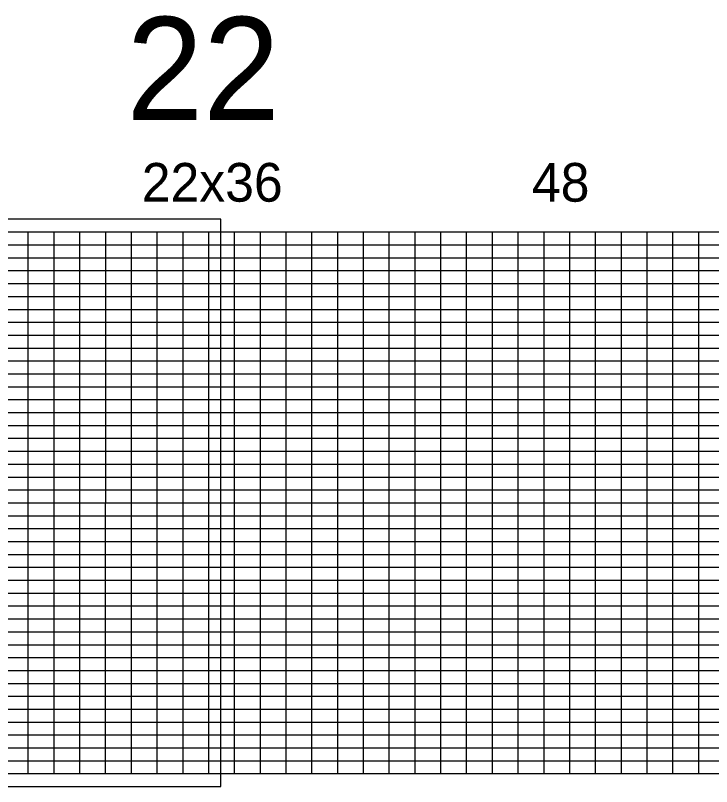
# Model space of a CAD drawing. Extents: x 1914168 to 1925341, y 720939 to 777401.
# Drawn here: x 1921169 to 1922519, y 733439 to 734934 of the extents above; entities that cross this region are included whole.
import ezdxf

# ---------------------------------------------------------------- set-up
doc = ezdxf.new("R2010")
doc.units = 0
for name, color, linetype in [('RD_PD_ALT1_CL', 7, 'Continuous'), ('RD_PD_WallFill', 7, 'Continuous'), ('RD_SHT_IplotShp', 7, 'Continuous')]:
    doc.layers.add(name, color=color, linetype=linetype)

msp = doc.modelspace()

# ---------------------------------------------------------------- linework, layer by layer
at = {"layer": 'RD_PD_WallFill'}
for p, q in [((1919844.1, 734514.2), (1925194.1, 734514.2)), ((1919844.1, 734514.2), (1921594.1, 734514.2)), ((1921194, 733464.2), (1921194.1, 734514.2)), ((1921194, 733464.2), (1921194.1, 734514.2)), ((1921244.1, 733464.2), (1921244.1, 734514.2)), ((1921244.1, 733464.2), (1921244.1, 734514.2)), ((1921294.1, 733464.2), (1921294.1, 734514.2)), ((1921294.1, 733464.2), (1921294.1, 734514.2)), ((1921344, 733464.2), (1921344.1, 734514.2)), ((1921344, 733464.2), (1921344.1, 734514.2)), ((1921394, 733464.2), (1921394.1, 734514.2)), ((1921394, 733464.2), (1921394.1, 734514.2)), ((1921444.1, 733464.2), (1921444.1, 734514.2)), ((1921444.1, 733464.2), (1921444.1, 734514.2)), ((1921494.1, 733464.2), (1921494.1, 734514.2)), ((1921494.1, 733464.2), (1921494.1, 734514.2)), ((1921544.1, 733464.2), (1921544.1, 734514.2)), ((1921544.1, 733464.2), (1921544.1, 734514.2)), ((1921594.1, 733464.2), (1921594.1, 734514.2)), ((1921594.1, 733464.2), (1921594.1, 734514.2)), ((1921644.1, 733464.2), (1921644.1, 734514.2)), ((1921644.1, 733464.2), (1921644.1, 734514.2)), ((1921694.1, 733464.2), (1921694.1, 734514.2)), ((1921694.1, 733464.2), (1921694.1, 734514.2)), ((1921744.1, 733464.2), (1921744.1, 734514.2)), ((1921744.1, 733464.2), (1921744.1, 734514.2)), ((1921794.1, 733464.2), (1921794.1, 734514.2)), ((1921794.1, 733464.2), (1921794.1, 734514.2)), ((1921844.1, 733464.2), (1921844.1, 734514.2)), ((1921844.1, 733464.2), (1921844.1, 734514.2)), ((1921894.1, 733464.2), (1921894.1, 734514.2)), ((1921894.1, 733464.2), (1921894.1, 734514.2)), ((1921944.1, 733464.2), (1921944.1, 734514.2)), ((1921944.1, 733464.2), (1921944.1, 734514.2)), ((1921994.1, 733464.2), (1921994.1, 734514.2)), ((1921994.1, 733464.2), (1921994.1, 734514.2)), ((1922044.1, 733464.2), (1922044.1, 734514.2)), ((1922044.1, 733464.2), (1922044.1, 734514.2)), ((1922094.1, 733464.2), (1922094.1, 734514.2)), ((1922094.1, 733464.2), (1922094.1, 734514.2)), ((1922144.1, 733464.2), (1922144.1, 734514.2)), ((1922144.1, 733464.2), (1922144.1, 734514.2)), ((1922194.1, 733464.2), (1922194.1, 734514.2)), ((1922194.1, 733464.2), (1922194.1, 734514.2)), ((1922244.1, 733464.2), (1922244.1, 734514.2)), ((1922244.1, 733464.2), (1922244.1, 734514.2)), ((1922294.1, 733464.2), (1922294.1, 734514.2)), ((1922294.1, 733464.2), (1922294.1, 734514.2)), ((1922344.1, 733464.2), (1922344.1, 734514.2)), ((1922344.1, 733464.2), (1922344.1, 734514.2)), ((1922394.1, 733464.2), (1922394.1, 734514.2)), ((1922394.1, 733464.2), (1922394.1, 734514.2)), ((1922444.1, 733464.2), (1922444.1, 734514.2)), ((1922444.1, 733464.2), (1922444.1, 734514.2)), ((1922494.1, 733464.2), (1922494.1, 734514.2)), ((1922494.1, 733464.2), (1922494.1, 734514.2)), ((1920294, 734489.2), (1925194.1, 734489.2)), ((1920294, 734489.2), (1925194.1, 734489.2)), ((1920294, 734464.2), (1925194.1, 734464.2)), ((1920294, 734439.2), (1925194.1, 734439.2)), ((1920294, 734414.2), (1925194.1, 734414.2)), ((1920294, 734389.2), (1925194.1, 734389.2)), ((1919844.1, 734364.2), (1925194.1, 734364.2)), ((1919844.1, 734339.2), (1925194.1, 734339.2)), ((1919844, 734314.2), (1925194.1, 734314.2)), ((1919844.1, 734289.2), (1925194.1, 734289.2)), ((1919844.1, 734264.2), (1925194.1, 734264.2)), ((1919844.1, 734239.2), (1925194.1, 734239.2)), ((1919844.1, 734214.2), (1925194.1, 734214.2)), ((1919844, 734189.2), (1925194.1, 734189.2)), ((1919844, 734164.2), (1925194.1, 734164.2)), ((1919844.1, 734139.2), (1925194.1, 734139.2)), ((1919844.1, 734114.2), (1925194.1, 734114.2)), ((1919844.1, 734089.2), (1925194.1, 734089.2)), ((1919844.1, 734064.2), (1925194.1, 734064.2)), ((1919844, 734039.2), (1925194.1, 734039.2)), ((1919844.1, 734014.2), (1925194.1, 734014.2)), ((1919844.1, 733989.2), (1925194.1, 733989.2)), ((1919844.1, 733964.2), (1925194.1, 733964.2)), ((1919844.1, 733939.2), (1925194.1, 733939.2)), ((1919844, 733914.2), (1925194.1, 733914.2)), ((1919844, 733889.2), (1925194.1, 733889.2)), ((1919844.1, 733864.2), (1925194.1, 733864.2)), ((1919844.1, 733839.2), (1925194.1, 733839.2)), ((1919844.1, 733814.2), (1925194.1, 733814.2)), ((1919844.1, 733789.2), (1925194.1, 733789.2)), ((1919844, 733764.2), (1925194.1, 733764.2)), ((1919844.1, 733739.2), (1925194.1, 733739.2)), ((1919844.1, 733714.2), (1925194.1, 733714.2)), ((1919844.1, 733689.2), (1925194.1, 733689.2)), ((1919844.1, 733664.2), (1925194.1, 733664.2)), ((1919844, 733639.2), (1925194.1, 733639.2)), ((1919844.1, 733614.2), (1925194.1, 733614.2)), ((1919844.1, 733589.2), (1925194.1, 733589.2)), ((1919844.1, 733564.2), (1925194.1, 733564.2)), ((1919844.1, 733539.2), (1925194.1, 733539.2)), ((1919844, 733514.2), (1925194.1, 733514.2)), ((1919844.1, 733489.2), (1925194.1, 733489.2)), ((1919844.1, 733464.2), (1925194.1, 733464.2)), ((1919844.1, 733464.2), (1925194.1, 733464.2))]:
    msp.add_line(p, q, dxfattribs=at)
at = {"layer": 'RD_SHT_IplotShp'}
msp.add_lwpolyline([(1919817.2, 733439.1), (1921567.2, 733439.1), (1921567.2, 734539.1), (1919817.2, 734539.1)], close=True, dxfattribs=at)

# ---------------------------------------------------------------- texts
at = {"layer": 'RD_PD_ALT1_CL'}
msp.add_text('22', height=200, dxfattribs=at).set_placement((1921384.5, 734730.9))
at = {"layer": 'RD_PD_WallFill'}
for s, p in [('22x36', (1921414.1, 734572.9)), ('22x36', (1921414.1, 734572.9)), ('48', (1922170.7, 734572.9)), ('48', (1922170.7, 734572.9))]:
    msp.add_text(s, height=75, dxfattribs=at).set_placement(p)

doc.saveas('drawing.dxf')
